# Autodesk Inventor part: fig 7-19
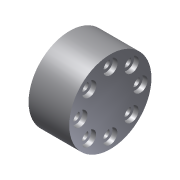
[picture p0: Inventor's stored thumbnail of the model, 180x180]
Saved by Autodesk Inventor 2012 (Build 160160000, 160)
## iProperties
Created: 2004-05
Part Number: fig 7-19
Document SubType Name: Modeling
Designer: CADCIM Technologies
Manufacturer: Standard
Standards Organization: Custom
Density: 1 g/cm^3
Material: Default
Author: CADCIM Technologies
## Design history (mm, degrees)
sketch "Sketch1"
  geometry: C1 r 17.175 at (0, 0)
  constraints: 1 centre point
extrude "Extrusion1" new body sketch "Sketch1" distance "d0" = 17; taper "d1" = 0 deg
sketch "Sketch2"
  geometry: 1 further point
hole "Hole1" sketch "Sketch2" at (12.571, -0.074) diameter "d2" = 3.5; stored, may be unused: countersink angle "d6" = 90 deg, drill point angle "d8" = 118 deg; dims "d3" = 6, "d4" = 6, "d5" = 2, "d7" = 8
pattern_circular "Circular Pattern1" dims angle "d11" = 360 deg
body "Solid1"
